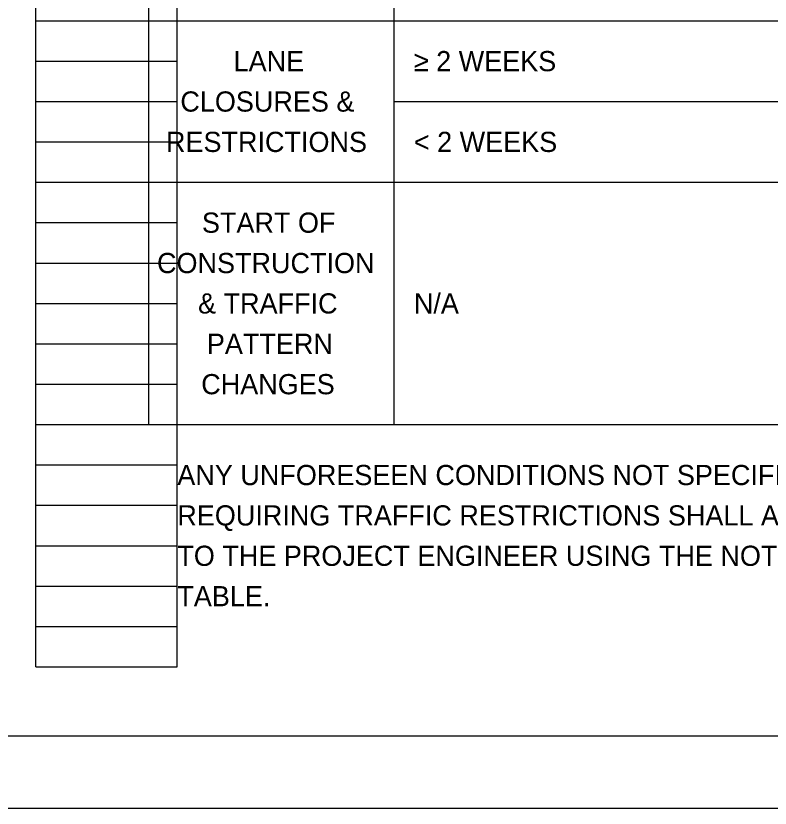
# Model space of a CAD drawing. Extents: x 0 to 34, y 0 to 22.
# Drawn here: x 23.54 to 28.77, y 0 to 5.49 of the extents above; entities that cross this region are included whole.
import ezdxf

# ---------------------------------------------------------------- set-up
doc = ezdxf.new("R2010")
doc.units = 0
for name, color, linetype in [('SH_Border', 7, 'Continuous'), ('SH_Cut_Line', 7, 'Continuous'), ('SH_Data', 7, 'Continuous'), ('SH_Text', 7, 'Continuous')]:
    doc.layers.add(name, color=color, linetype=linetype)

msp = doc.modelspace()

# ---------------------------------------------------------------- linework, layer by layer
at = {"layer": 'SH_Border'}
msp.add_lwpolyline([(1.5, 21.5), (33.5, 21.5), (33.5, 0.5), (1.5, 0.5)], close=True, dxfattribs=at)
at = {"layer": 'SH_Cut_Line'}
msp.add_lwpolyline([(0, 0), (34, 0), (34, 22), (0, 22)], close=True, dxfattribs=at)
at = {"layer": 'SH_Data'}
for p, q in [((23.68, 0.98), (23.68, 21.14)), ((24.66, 0.98), (24.66, 21.14)), ((24.46, 7.98), (24.46, 2.66)), ((26.16, 7.7), (26.16, 2.66)), ((23.68, 5.46), (24.66, 5.46)), ((24.46, 5.46), (31.16, 5.46)), ((23.68, 5.18), (24.66, 5.18)), ((23.68, 4.9), (24.66, 4.9)), ((26.16, 4.9), (31.16, 4.9)), ((23.68, 4.62), (24.66, 4.62)), ((23.68, 4.34), (24.66, 4.34)), ((24.46, 4.34), (31.16, 4.34)), ((23.68, 4.06), (24.66, 4.06)), ((23.68, 3.78), (24.66, 3.78)), ((23.68, 3.5), (24.66, 3.5)), ((23.68, 3.22), (24.66, 3.22)), ((23.68, 2.94), (24.66, 2.94)), ((23.68, 2.66), (24.66, 2.66)), ((24.46, 2.66), (31.16, 2.66)), ((23.68, 2.38), (24.66, 2.38)), ((23.68, 2.1), (24.66, 2.1)), ((23.68, 1.82), (24.66, 1.82)), ((23.68, 1.54), (24.66, 1.54)), ((23.68, 1.26), (24.66, 1.26)), ((23.68, 0.98), (24.66, 0.98))]:
    msp.add_line(p, q, dxfattribs=at)

# ---------------------------------------------------------------- texts
for s, p in [('LANE', (25.0501, 5.11)), ('CLOSURES & ', (24.681, 4.83)), ('RESTRICTIONS', (24.5813, 4.55)), ('START OF', (24.8306, 3.99)), ('CONSTRUCTION', (24.519, 3.71)), ('& TRAFFIC', (24.8038, 3.43)), ('PATTERN ', (24.8649, 3.15)), ('CHANGES', (24.8258, 2.87))]:
    msp.add_text(s, height=0.14, dxfattribs=at).set_placement(p)
at = {"layer": 'SH_Text'}
for s, p in [('≥ 2 WEEKS', (26.3, 5.11)), ('< 2 WEEKS', (26.3, 4.55)), ('N/A', (26.3, 3.43)), ('ANY UNFORESEEN CONDITIONS NOT SPECIFIED IN THE PLANS ', (24.66, 2.24)), ('REQUIRING TRAFFIC RESTRICTIONS SHALL ALSO BE REPORTED ', (24.66, 1.96)), ('TO THE PROJECT ENGINEER USING THE NOTIFICATION TIME ', (24.66, 1.68)), ('TABLE.', (24.66, 1.4))]:
    msp.add_text(s, height=0.14, dxfattribs=at).set_placement(p)

doc.saveas('drawing.dxf')
